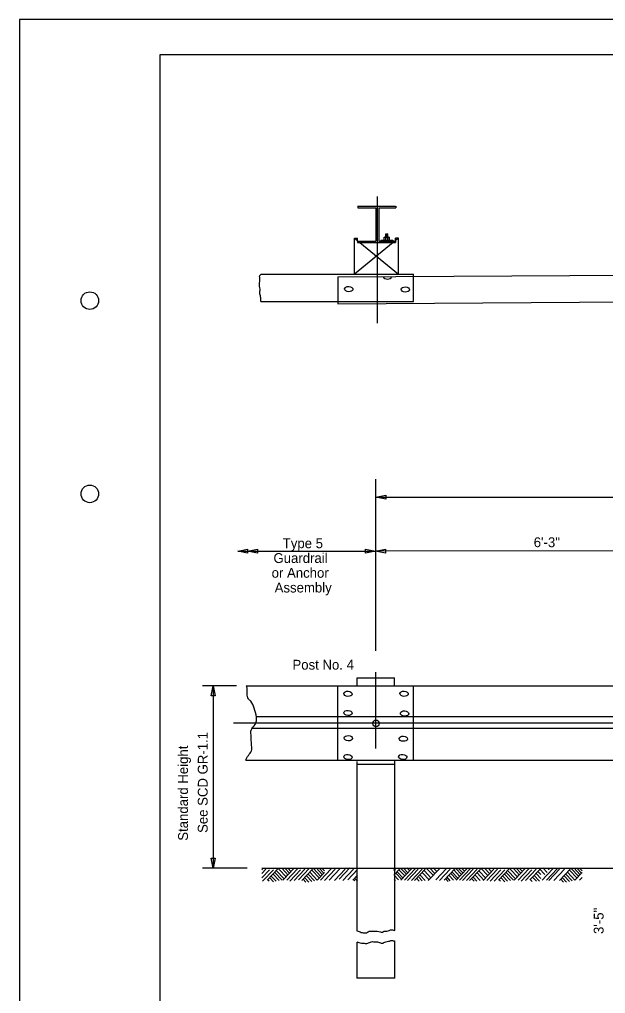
# Model space of a CAD drawing. Extents: x 0 to 34, y 0 to 22.
# Drawn here: x 0 to 8.33, y 8.14 to 22 of the extents above; entities that cross this region are included whole.
import ezdxf

# ---------------------------------------------------------------- set-up
doc = ezdxf.new("R2010")
doc.units = 0
for name, color, linetype in [('SH_Border', 7, 'Continuous'), ('SH_Cut_Line', 7, 'Continuous'), ('ST_Details', 7, 'Continuous'), ('ST_Text', 7, 'Continuous')]:
    doc.layers.add(name, color=color, linetype=linetype)

msp = doc.modelspace()

# ---------------------------------------------------------------- linework, layer by layer
at = {"layer": 'SH_Border'}
msp.add_lwpolyline([(2, 21.5), (33.5, 21.5), (33.5, 0.5), (2, 0.5)], close=True, dxfattribs=at)
for centre in [(1, 18), (1, 15.25)]:
    msp.add_circle(centre, 0.125, dxfattribs=at)
at = {"layer": 'SH_Cut_Line'}
msp.add_lwpolyline([(0, 0), (34, 0), (34, 22), (0, 22)], close=True, dxfattribs=at)
at = {"layer": 'ST_Details'}
for p, q in [((5.09, 17.68), (5.09, 19.48)), ((4.808, 19.345), (5.349, 19.345)), ((4.811, 19.344), (4.811, 19.322)), ((4.811, 19.322), (5.068, 19.322)), ((5.07, 19.319), (5.07, 18.847)), ((5.11, 19.322), (5.352, 19.322)), ((5.11, 19.321), (5.11, 18.845)), ((5.352, 19.344), (5.352, 19.322)), ((4.763, 18.374), (4.763, 18.889)), ((4.763, 18.889), (4.807, 18.889)), ((4.763, 18.889), (4.807, 18.853)), ((4.807, 18.846), (4.807, 18.889)), ((5.139, 18.861), (5.31, 18.861)), ((5.139, 18.861), (5.139, 18.846)), ((5.184, 18.902), (5.264, 18.902)), ((5.184, 18.862), (5.184, 18.902)), ((5.209, 18.862), (5.209, 18.902)), ((5.211, 18.903), (5.211, 18.949)), ((5.211, 18.949), (5.24, 18.949)), ((5.211, 18.941), (5.24, 18.941)), ((5.211, 18.934), (5.24, 18.934)), ((5.211, 18.927), (5.24, 18.927)), ((5.211, 18.92), (5.24, 18.92)), ((5.211, 18.914), (5.24, 18.914)), ((5.211, 18.907), (5.24, 18.907)), ((5.239, 18.862), (5.239, 18.902)), ((5.24, 18.903), (5.24, 18.949)), ((5.264, 18.862), (5.264, 18.902)), ((5.31, 18.861), (5.31, 18.846)), ((5.349, 18.846), (5.349, 18.889)), ((5.39, 18.889), (5.349, 18.889)), ((5.39, 18.889), (5.349, 18.855)), ((5.39, 18.374), (5.39, 18.889)), ((5.315, 18.827), (4.763, 18.374)), ((4.807, 18.846), (4.807, 18.827)), ((4.807, 18.846), (5.068, 18.846)), ((4.807, 18.827), (5.349, 18.827)), ((4.838, 18.827), (5.39, 18.374)), ((5.108, 18.846), (5.349, 18.846)), ((5.349, 18.846), (5.349, 18.827)), ((3.433, 18.374), (5.603, 18.374)), ((4.527, 18.338), (11.012, 18.374)), ((4.527, 18.338), (4.527, 17.954)), ((5.603, 17.988), (5.603, 18.374)), ((3.433, 17.988), (4.527, 17.988)), ((4.527, 17.954), (10.414, 17.993)), ((4.527, 17.988), (5.603, 17.988)), ((4.804, 12.521), (4.804, 12.631)), ((4.804, 12.631), (5.335, 12.631)), ((5.07, 11.629), (5.07, 12.712)), ((5.335, 12.521), (5.335, 12.631)), ((3.226, 12.517), (4.527, 12.517)), ((4.527, 12.517), (12.695, 12.517)), ((4.527, 11.46), (4.527, 12.514)), ((5.603, 11.46), (5.603, 12.517)), ((27.557, 12.077), (3.369, 12.077)), ((3.044, 11.99), (30.061, 11.99)), ((5.069, 11.983), (5.069, 11.983)), ((27.557, 11.912), (3.304, 11.912)), ((3.217, 11.46), (4.527, 11.46)), ((4.527, 11.46), (8.303, 11.46)), ((4.804, 9.927), (4.804, 11.444)), ((4.804, 11.406), (5.335, 11.406)), ((5.337, 9.925), (5.337, 11.46)), ((8.303, 11.46), (12.695, 11.46)), ((3.447, 9.925), (5.337, 9.925)), ((3.447, 9.9), (3.455, 9.908)), ((3.447, 9.847), (3.505, 9.908)), ((3.447, 9.788), (3.554, 9.901)), ((3.458, 9.74), (3.61, 9.901)), ((3.52, 9.753), (3.673, 9.915)), ((3.694, 9.747), (3.603, 9.843)), ((3.735, 9.753), (3.625, 9.869)), ((3.759, 9.776), (3.656, 9.885)), ((3.795, 9.798), (3.687, 9.912)), ((3.821, 9.826), (3.734, 9.918)), ((3.744, 9.753), (3.896, 9.915)), ((3.838, 9.854), (3.777, 9.918)), ((3.8, 9.753), (3.952, 9.915)), ((3.861, 9.879), (3.821, 9.922)), ((3.843, 9.74), (3.996, 9.901)), ((3.906, 9.747), (4.058, 9.908)), ((3.968, 9.76), (4.12, 9.921)), ((4.015, 9.747), (4.167, 9.908)), ((4.235, 9.756), (4.133, 9.864)), ((4.262, 9.787), (4.162, 9.893)), ((4.283, 9.812), (4.182, 9.918)), ((4.305, 9.835), (4.222, 9.923)), ((4.232, 9.753), (4.338, 9.865)), ((4.328, 9.853), (4.266, 9.918)), ((4.28, 9.753), (4.432, 9.915)), ((4.338, 9.887), (4.302, 9.925)), ((4.337, 9.75), (4.489, 9.911)), ((4.402, 9.753), (4.554, 9.915)), ((4.479, 9.747), (4.631, 9.908)), ((4.547, 9.766), (4.699, 9.928)), ((4.597, 9.747), (4.749, 9.908)), ((4.671, 9.76), (4.808, 9.905)), ((4.804, 9.033), (4.804, 9.927)), ((5.325, 9.826), (5.408, 9.915)), ((5.325, 9.892), (5.34, 9.908)), ((5.33, 9.895), (5.345, 9.911)), ((5.337, 9.925), (10.623, 9.925)), ((5.338, 9.042), (5.338, 9.927)), ((5.432, 9.769), (5.353, 9.852)), ((5.452, 9.787), (5.372, 9.872)), ((5.48, 9.814), (5.397, 9.901)), ((5.424, 9.753), (5.576, 9.915)), ((5.504, 9.837), (5.425, 9.921)), ((5.523, 9.86), (5.462, 9.924)), ((5.473, 9.753), (5.626, 9.915)), ((5.546, 9.889), (5.509, 9.928)), ((5.517, 9.747), (5.669, 9.908)), ((5.573, 9.747), (5.725, 9.908)), ((5.616, 9.747), (5.769, 9.908)), ((5.824, 9.758), (5.73, 9.859)), ((5.85, 9.788), (5.758, 9.885)), ((5.876, 9.829), (5.789, 9.921)), ((5.814, 9.75), (5.981, 9.926)), ((5.908, 9.847), (5.832, 9.928)), ((5.933, 9.876), (5.885, 9.928)), ((5.922, 9.76), (6.075, 9.921)), ((5.972, 9.747), (6.125, 9.908)), ((6.041, 9.753), (6.193, 9.915)), ((6.212, 9.766), (6.133, 9.849)), ((6.232, 9.784), (6.152, 9.869)), ((6.259, 9.811), (6.176, 9.899)), ((6.284, 9.834), (6.204, 9.918)), ((6.208, 9.753), (6.361, 9.915)), ((6.303, 9.857), (6.242, 9.922)), ((6.258, 9.753), (6.411, 9.915)), ((6.325, 9.886), (6.288, 9.925)), ((6.302, 9.747), (6.454, 9.908)), ((6.358, 9.747), (6.51, 9.908)), ((6.401, 9.747), (6.554, 9.908)), ((6.604, 9.755), (6.509, 9.856)), ((6.629, 9.785), (6.537, 9.882)), ((6.655, 9.826), (6.568, 9.918)), ((6.594, 9.747), (6.746, 9.908)), ((6.688, 9.844), (6.612, 9.925)), ((6.644, 9.747), (6.796, 9.908)), ((6.713, 9.874), (6.665, 9.925)), ((6.693, 9.74), (6.846, 9.901)), ((6.749, 9.74), (6.902, 9.901)), ((6.812, 9.753), (6.964, 9.915)), ((6.985, 9.747), (6.895, 9.843)), ((7.026, 9.753), (6.916, 9.869)), ((7.051, 9.776), (6.947, 9.885)), ((7.086, 9.798), (6.979, 9.912)), ((7.113, 9.826), (7.025, 9.918)), ((7.035, 9.753), (7.188, 9.915)), ((7.129, 9.854), (7.069, 9.918)), ((7.091, 9.753), (7.244, 9.915)), ((7.153, 9.879), (7.112, 9.922)), ((7.135, 9.74), (7.287, 9.901)), ((7.197, 9.747), (7.349, 9.908)), ((7.259, 9.76), (7.412, 9.921)), ((7.413, 9.778), (7.351, 9.843)), ((7.413, 9.834), (7.376, 9.872)), ((7.47, 9.836), (7.392, 9.918)), ((7.432, 9.753), (7.585, 9.915)), ((7.504, 9.863), (7.443, 9.928)), ((7.494, 9.753), (7.647, 9.915)), ((7.532, 9.899), (7.51, 9.923)), ((7.53, 9.747), (7.682, 9.908)), ((7.598, 9.747), (7.751, 9.908)), ((7.679, 9.747), (7.832, 9.908)), ((7.9, 9.756), (7.798, 9.864)), ((7.926, 9.787), (7.827, 9.893)), ((7.948, 9.812), (7.847, 9.918)), ((7.97, 9.835), (7.887, 9.923)), ((7.897, 9.753), (8.003, 9.865)), ((7.993, 9.853), (7.931, 9.918)), ((8.003, 9.887), (7.966, 9.925)), ((3.55, 9.738), (3.529, 9.76)), ((3.612, 9.732), (3.56, 9.787)), ((3.649, 9.739), (3.581, 9.81)), ((4.073, 9.726), (4.034, 9.768)), ((4.117, 9.725), (4.056, 9.789)), ((4.158, 9.733), (4.08, 9.815)), ((4.197, 9.744), (4.107, 9.839)), ((4.74, 9.753), (4.808, 9.826)), ((4.768, 9.743), (4.749, 9.763)), ((4.805, 9.741), (4.766, 9.782)), ((4.808, 9.782), (4.788, 9.803)), ((5.392, 9.758), (5.33, 9.824)), ((5.348, 9.749), (5.33, 9.768)), ((5.685, 9.741), (5.647, 9.782)), ((5.727, 9.743), (5.677, 9.796)), ((5.77, 9.749), (5.698, 9.826)), ((5.876, 9.821), (5.874, 9.822)), ((5.881, 9.823), (5.88, 9.825)), ((6.097, 9.736), (6.058, 9.777)), ((6.127, 9.746), (6.08, 9.796)), ((6.172, 9.756), (6.108, 9.823)), ((6.465, 9.738), (6.426, 9.779)), ((6.506, 9.74), (6.456, 9.793)), ((6.55, 9.747), (6.478, 9.823)), ((6.66, 9.821), (6.659, 9.822)), ((6.841, 9.738), (6.821, 9.76)), ((6.903, 9.732), (6.851, 9.787)), ((6.94, 9.739), (6.873, 9.81)), ((7.289, 9.735), (7.262, 9.763)), ((7.351, 9.738), (7.296, 9.796)), ((7.395, 9.741), (7.317, 9.823)), ((7.738, 9.726), (7.698, 9.768)), ((7.781, 9.725), (7.72, 9.789)), ((7.822, 9.733), (7.745, 9.815)), ((7.861, 9.744), (7.771, 9.839)), ((7.965, 9.753), (8.003, 9.793)), ((4.8, 8.361), (4.8, 8.87)), ((5.338, 8.361), (5.338, 8.879)), ((5.338, 8.361), (4.799, 8.361))]:
    msp.add_line(p, q, dxfattribs=at)
for centre, major_axis, ratio, start_param, end_param in [((5.197, 18.888), (0, -0.0145), 0.944544, 1.407332, 4.875992), ((5.225, 18.888), (0, -0.0151), 0.944544, 1.46268, 4.897879), ((5.251, 18.888), (0, -0.0127), 0.944544, 1.349184, 4.841957), ((5.23, 18.343), (-0.059, 0.0039), 0.623742, 0.247265, 3.105972)]:
    msp.add_ellipse(centre, major_axis=major_axis, ratio=ratio, start_param=start_param, end_param=end_param, dxfattribs=at)
for centre, major_axis, ratio in [((4.683, 18.163), (-0.059, 0.0039), 0.623742), ((5.487, 18.158), (-0.059, 0.0039), 0.623742), ((4.671, 12.406), (-0.059, 0.0039), 0.623742), ((5.47, 12.406), (-0.059, 0.0039), 0.623742), ((4.671, 12.133), (-0.059, 0.0039), 0.623742), ((5.476, 12.126), (-0.059, 0.0039), 0.623742), ((5.07, 11.984), (0, 0.0478), 0.944544), ((4.677, 11.773), (-0.059, 0.0039), 0.623742), ((5.458, 11.766), (-0.059, 0.0039), 0.623742), ((4.671, 11.506), (-0.059, 0.0039), 0.623742), ((5.451, 11.506), (-0.059, 0.0039), 0.623742)]:
    msp.add_ellipse(centre, major_axis=major_axis, ratio=ratio, dxfattribs=at)
for points in [[(3.433, 17.988), (3.431, 18.04), (3.427, 18.067), (3.417, 18.095), (3.42, 18.133), (3.422, 18.162), (3.415, 18.205), (3.412, 18.238), (3.419, 18.272), (3.42, 18.292), (3.417, 18.33), (3.414, 18.344), (3.42, 18.357), (3.433, 18.374)], [(3.217, 11.46), (3.256, 11.528), (3.3, 11.595), (3.3, 11.668), (3.294, 11.821), (3.294, 11.888), (3.351, 11.968), (3.37, 12.074), (3.338, 12.201), (3.288, 12.301), (3.256, 12.334), (3.237, 12.408), (3.231, 12.507), (3.226, 12.517)], [(4.797, 9.032), (4.8, 9.032), (4.859, 9.011), (4.914, 9.003), (4.924, 9.003), (4.973, 9.026), (5.041, 9.026), (5.135, 9.018), (5.152, 9.012), (5.175, 9.022), (5.223, 9.029), (5.294, 9.048), (5.34, 9.036)], [(4.797, 8.877), (4.827, 8.867), (4.904, 8.855), (4.953, 8.855), (5.003, 8.878), (5.036, 8.878), (5.107, 8.872), (5.157, 8.855), (5.211, 8.878), (5.25, 8.884), (5.294, 8.896), (5.337, 8.884)]]:
    msp.add_spline(points, degree=3, dxfattribs=at)
at = {"layer": 'ST_Text'}
for p, q in [((5.07, 13.017), (5.07, 15.46)), ((5.07, 15.205), (25.314, 15.205)), ((3.104, 14.436), (5.063, 14.436)), ((10.34, 14.438), (5.063, 14.436)), ((3.086, 12.517), (2.604, 12.517)), ((2.755, 12.517), (2.755, 9.925)), ((3.237, 9.925), (2.604, 9.925))]:
    msp.add_line(p, q, dxfattribs=at)
for points in [[(5.21, 15.233), (5.21, 15.177), (5.07, 15.205)], [(3.244, 14.464), (3.244, 14.408), (3.104, 14.436)], [(3.384, 14.464), (3.384, 14.408), (3.244, 14.436)], [(4.923, 14.408), (4.923, 14.464), (5.063, 14.436)], [(5.203, 14.464), (5.203, 14.408), (5.063, 14.436)], [(2.783, 12.377), (2.727, 12.377), (2.755, 12.517)], [(2.727, 10.065), (2.783, 10.065), (2.755, 9.925)]]:
    msp.add_lwpolyline(points, close=True, dxfattribs=at)

# ---------------------------------------------------------------- texts
for s, p in [('Type 5', (3.744, 14.477)), ('6\'-3"', (7.313, 14.492)), ('Guardrail', (3.612, 14.267)), ('or Anchor', (3.586, 14.057)), ('Assembly', (3.629, 13.847)), ('Post No. 4', (3.882, 12.749))]:
    msp.add_text(s, height=0.14, dxfattribs=at).set_placement(p)
for s, p in [('See SCD GR-1.1', (2.676, 10.426)), ('Standard Height', (2.396, 10.315)), ('3\'-5"', (8.307, 8.988))]:
    msp.add_text(s, height=0.14, rotation=90, dxfattribs=at).set_placement(p)

doc.saveas('drawing.dxf')
